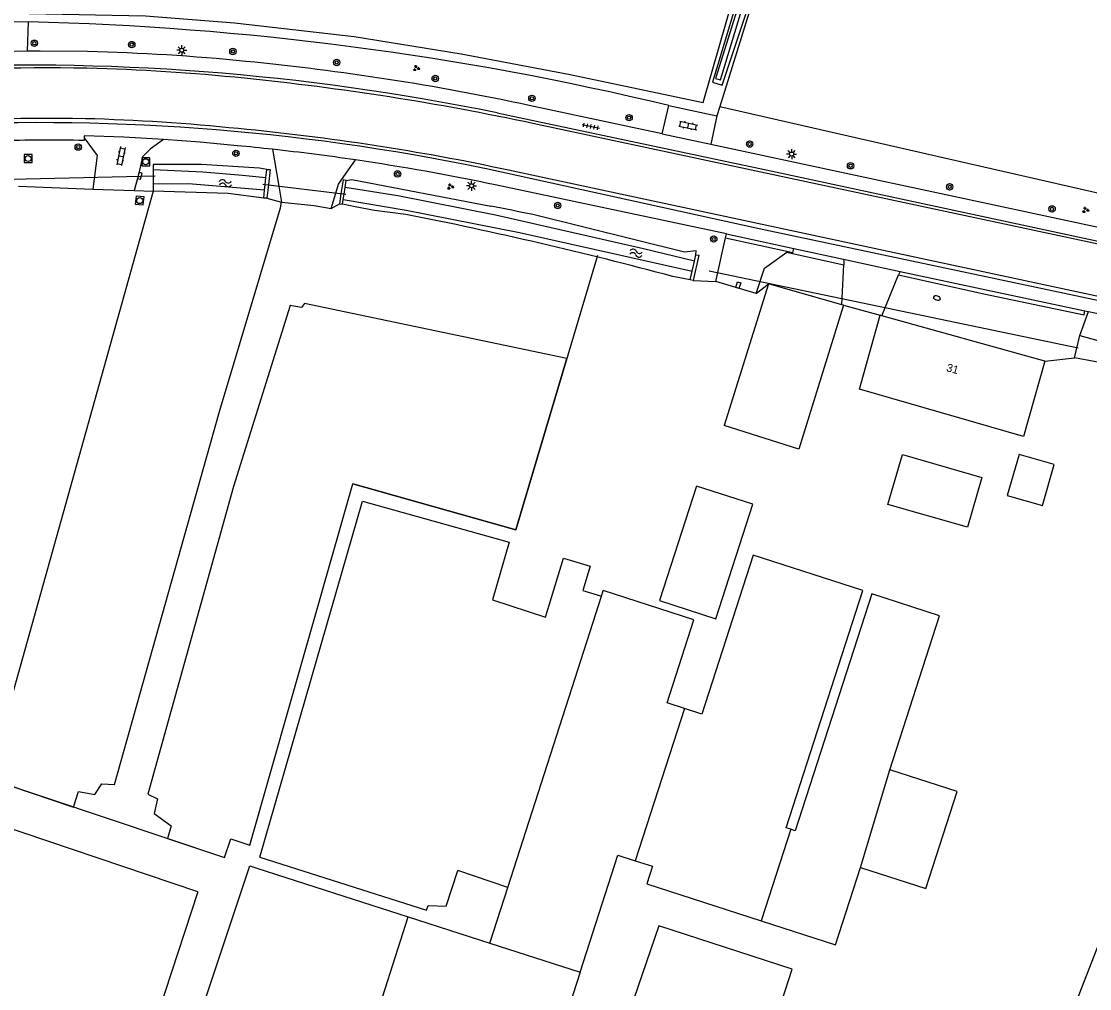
# Model space of a CAD drawing. Extents: x 136000 to 141014, y 402000 to 403500.
# Drawn here: x 136659.8 to 136793.3, y 402085 to 402205.8 of the extents above; entities that cross this region are included whole.
import ezdxf

# ---------------------------------------------------------------- set-up
doc = ezdxf.new("R2010")
doc.units = 0
for name, color, linetype in [('gg-afsc-draadraster', 7, 'Continuous'), ('gg-afsc-erfafscheiding', 7, 'Continuous'), ('gg-afsc-lijn draadraster', 7, 'Continuous'), ('gg-anno-huisnummerreeks BGT', 7, 'Continuous'), ('gg-bbg-bijgebouw', 7, 'Continuous'), ('gg-bbg-gedigitaliseerde bebouwing', 7, 'Continuous'), ('gg-bbg-gedigitaliseerde bijgebouw', 7, 'Continuous'), ('gg-bbg-hoofdgebouw', 7, 'Continuous'), ('gg-bbg-open loods', 7, 'Continuous'), ('gg-bbg-tussenscheiding', 7, 'Continuous'), ('gg-knt-bronhoudergrens', 7, 'Continuous'), ('gg-knt-verharding', 7, 'Continuous'), ('gg-kntw-bovenkant insteek waterloop', 7, 'Continuous'), ('gg-kntw-waterlijn', 7, 'Continuous'), ('gg-kwrk-duiker nz buis', 7, 'Continuous'), ('gg-kwrk-keermuur', 7, 'Continuous'), ('gt-grn-groengrens', 7, 'Continuous'), ('gt-grn-vlakafsluiter', 7, 'Continuous'), ('gt-symb-boom', 7, 'Continuous'), ('gt-symb-brandkraan', 7, 'Continuous'), ('gt-symb-groenvak', 7, 'Continuous'), ('gt-symb-klinker verharding', 7, 'Continuous'), ('gt-symb-kolk', 7, 'Continuous'), ('gt-symb-kolk center center', 7, 'Continuous'), ('gt-symb-lichtmast', 7, 'Continuous'), ('gt-symb-rioolschacht', 7, 'Continuous'), ('gt-symb-tegel verharding', 7, 'Continuous'), ('gt-symb-watersymbool', 7, 'Continuous')]:
    doc.layers.add(name, color=color, linetype=linetype)

# ---------------------------------------------------------------- blocks, each defined once
blk = doc.blocks.new('gt0-BR')
at = {"layer": 'gt-symb-brandkraan'}
for centre, radius, start, end in [((-0.24, 0), 0.206, 107.5669, 252.4331), ((0.6, -2.66), 3, 106.892, 107.5669), ((0, -0.69), 0.938, 73.108, 106.892), ((-0.6, -2.66), 3, 72.4331, 73.108), ((0.24, 0), 0.206, 287.567, 72.4331), ((0.6, 2.66), 3, 252.4331, 253.108), ((0, 0.69), 0.938, 253.108, 286.8921), ((-0.6, 2.66), 3, 286.8921, 287.567)]:
    blk.add_arc(centre, radius, start, end, dxfattribs=at)
blk = doc.blocks.new('gt0-KOLKCC')
at = {"layer": 'gt-symb-kolk center center'}
blk.add_lwpolyline([(-0.37, 0.2), (0.38, 0.2), (0.38, -0.2), (-0.37, -0.2)], close=True, dxfattribs=at)
blk = doc.blocks.new('gt0-GRVAK')
at = {"layer": 'gt-symb-groenvak'}
for p, q in [((-0.11, 0.19), (-0.23, 0.24)), ((-0.18, 0.15), (0.09, 0.15)), ((-0.09, 0.21), (-0.16, 0.32)), ((-0.05, 0.21), (-0.05, 0.39)), ((0, 0.21), (0.06, 0.32)), ((0.02, 0.19), (0.13, 0.24)), ((0.26, -0.05), (0.2, 0.06)), ((0.31, -0.05), (0.31, 0.13)), ((0.35, -0.05), (0.41, 0.06)), ((-0.24, -0.23), (-0.36, -0.18)), ((-0.32, -0.26), (-0.05, -0.26)), ((-0.23, -0.21), (-0.29, -0.1)), ((-0.18, -0.2), (-0.18, -0.02)), ((-0.14, -0.21), (-0.07, -0.1)), ((-0.12, -0.23), (0, -0.18)), ((0.24, -0.07), (0.12, -0.02)), ((0.17, -0.11), (0.44, -0.11)), ((0.37, -0.07), (0.49, -0.02))]:
    blk.add_line(p, q, dxfattribs=at)
blk = doc.blocks.new('gt0-BOOM')
at = {"layer": 'gt-symb-boom'}
for radius in [0.4, 0.2]:
    blk.add_circle((0, 0), radius, dxfattribs=at)
blk = doc.blocks.new('gt0-WA')
at = {"layer": 'gt-symb-watersymbool'}
for centre, start, end in [((-0.32, 0.02), 28.0725, 151.9275), ((0.43, 0.42), 208.0725, 331.9275), ((-0.32, -0.43), 28.0725, 151.9275), ((0.43, -0.03), 208.0725, 331.9275)]:
    blk.add_arc(centre, 0.425, start, end, dxfattribs=at)
blk = doc.blocks.new('gt0-LMAST')
at = {"layer": 'gt-symb-lichtmast'}
for p, q in [((-0.18, 0.17), (-0.45, 0.44)), ((0, 0.25), (0, 0.62)), ((0.17, 0.17), (0.44, 0.44)), ((-0.25, 0), (-0.63, 0)), ((-0.18, -0.18), (-0.45, -0.45)), ((0, -0.25), (0, -0.63)), ((0.44, -0.45), (0.17, -0.18)), ((0.25, 0), (0.62, 0))]:
    blk.add_line(p, q, dxfattribs=at)
blk.add_circle((0, 0), 0.25, dxfattribs=at)
blk = doc.blocks.new('gt0-TEG1')
at = {"layer": 'gt-symb-tegel verharding'}
for p, q in [((-1.12, 0), (1.12, 0)), ((-0.9, -0.25), (-0.9, 0.25)), ((-0.45, -0.25), (-0.45, 0.25)), ((0, -0.25), (0, 0.25)), ((0.45, -0.25), (0.45, 0.25)), ((0.9, -0.25), (0.9, 0.25))]:
    blk.add_line(p, q, dxfattribs=at)
blk = doc.blocks.new('gt0-KL1')
at = {"layer": 'gt-symb-klinker verharding'}
for p, q in [((-1.15, 0.3), (1.15, 0.3)), ((-1, -0.3), (-1, 0.3)), ((-0.5, 0.3), (-0.5, 0.45)), ((0, -0.3), (0, 0.3)), ((0.5, 0.3), (0.5, 0.45)), ((1, -0.3), (1, 0.3)), ((-1.15, -0.3), (1.15, -0.3)), ((-0.5, -0.45), (-0.5, -0.3)), ((0.5, -0.45), (0.5, -0.3))]:
    blk.add_line(p, q, dxfattribs=at)
blk = doc.blocks.new('gt0-RS')
at = {"layer": 'gt-symb-rioolschacht'}
blk.add_lwpolyline([(-0.5, -0.5), (0.5, -0.5), (0.5, 0.5), (-0.5, 0.5)], close=True, dxfattribs=at)
blk.add_circle((0, 0), 0.375, dxfattribs=at)
blk = doc.blocks.new('gt0-KOLK')
at = {"layer": 'gt-symb-kolk'}
blk.add_lwpolyline([(0, 0), (0.38, 0), (0.38, 0.4), (-0.37, 0.4), (-0.37, 0), (0, 0)], dxfattribs=at)

msp = doc.modelspace()

# ---------------------------------------------------------------- linework, layer by layer
at = {"layer": 'gg-afsc-draadraster'}
for p, q in [((136689.6, 402101.38), (136702.42, 402145.89)), ((136702.42, 402145.89), (136720.76, 402140.75))]:
    msp.add_line(p, q, dxfattribs=at)
at = {"layer": 'gg-afsc-erfafscheiding'}
for p, q in [((136659.43, 402185.22), (136668.71, 402184.88)), ((136668.71, 402184.88), (136673.89, 402184.69)), ((136673.89, 402184.69), (136676.28, 402184.61)), ((136792.06, 402166.6), (136793.15, 402169.58))]:
    msp.add_line(p, q, dxfattribs=at)
msp.add_arc((136651.79, 401826.29), 379.58, 76.4502, 88.6591, dxfattribs=at)
at = {"layer": 'gg-afsc-lijn draadraster'}
for p, q in [((136689.6, 402101.38), (136702.42, 402145.89)), ((136702.42, 402145.89), (136720.76, 402140.75))]:
    msp.add_line(p, q, dxfattribs=at)
for points in [[(136676.28, 402184.61), (136655.68, 402111.23), (136685.18, 402101.34), (136685.97, 402103.7), (136688.33, 402102.91), (136701.2, 402148.06)], [(136731.81, 402176.59), (136721.6, 402142.3), (136701.2, 402148.06)]]:
    msp.add_lwpolyline(points, dxfattribs=at)
at = {"layer": 'gg-bbg-bijgebouw'}
for p, q in [((136762.33, 402170.41), (136753.18, 402173.02)), ((136762.53, 402170.35), (136762.33, 402170.41)), ((136730.86, 402129.6), (136732.28, 402134.02)), ((136732.28, 402134.02), (136732.5, 402134.71)), ((136720.57, 402097.62), (136730.86, 402129.6)), ((136673.5, 402055.65), (136688.33, 402100.31)), ((136688.33, 402100.31), (136689.21, 402100.03)), ((136689.21, 402100.03), (136701.25, 402096.15)), ((136718.33, 402090.66), (136720.57, 402097.62)), ((136701.25, 402096.15), (136708.15, 402093.93)), ((136708.15, 402093.93), (136718.33, 402090.66))]:
    msp.add_line(p, q, dxfattribs=at)
msp.add_lwpolyline([(136784.93, 402066.17), (136803.05, 402112.68), (136826.4, 402103.59), (136808.29, 402057.08), (136784.93, 402066.17)], dxfattribs=at)
at = {"layer": 'gg-bbg-gedigitaliseerde bebouwing'}
msp.add_lwpolyline([(136787.69, 402163.36), (136785.02, 402153.97), (136764.52, 402159.86), (136767.13, 402169.1)], dxfattribs=at)
at = {"layer": 'gg-bbg-gedigitaliseerde bijgebouw'}
msp.add_line((136753.18, 402173.02), (136747.64, 402155.33), dxfattribs=at)
for points in [[(136762.53, 402170.35), (136756.95, 402152.38), (136747.64, 402155.33)], [(136768.09, 402145.48), (136769.89, 402151.71), (136779.84, 402148.85), (136778.05, 402142.62), (136768.09, 402145.48)], [(136783, 402146.6), (136787.41, 402145.34), (136788.88, 402150.45), (136784.47, 402151.72), (136783, 402146.6)], [(136739.55, 402133.45), (136746.6, 402131.18), (136751.22, 402145.49), (136744.17, 402147.77), (136739.55, 402133.45)], [(136755.94, 402104.88), (136755.38, 402105.06), (136764.95, 402134.72), (136751.24, 402139.15), (136744.82, 402119.27), (136742.65, 402119.97)], [(136742.65, 402119.97), (136740.49, 402120.66), (136743.84, 402131.05), (136732.5, 402134.71)], [(136768.33, 402112.32), (136774.53, 402131.54), (136766.06, 402134.28), (136756.51, 402104.7), (136755.94, 402104.88)], [(136764.65, 402100.1), (136772.81, 402097.46), (136776.74, 402109.61), (136768.33, 402112.32)], [(136729.62, 402087.02), (136734.35, 402101.65), (136736.51, 402100.95)], [(136736.51, 402100.95), (136738.68, 402100.25), (136737.96, 402098.04), (136752.24, 402093.42)], [(136752.24, 402093.42), (136761.52, 402090.43), (136764.65, 402100.1)], [(136729.62, 402087.02), (136715.15, 402042.2), (136693.68, 402049.13)]]:
    msp.add_lwpolyline(points, dxfattribs=at)
at = {"layer": 'gg-bbg-hoofdgebouw'}
for p, q in [((136767.32, 402169.05), (136767.13, 402169.1)), ((136787.69, 402163.36), (136767.32, 402169.05))]:
    msp.add_line(p, q, dxfattribs=at)
at = {"layer": 'gg-bbg-open loods'}
msp.add_lwpolyline([(136721.26, 402039.66), (136738.77, 402033.66), (136756.12, 402087.41), (136739.46, 402092.8), (136721.26, 402039.66)], dxfattribs=at)
at = {"layer": 'gg-bbg-tussenscheiding'}
for p, q in [((136742.65, 402119.97), (136736.51, 402100.95)), ((136764.65, 402100.1), (136768.33, 402112.32)), ((136755.94, 402104.88), (136752.24, 402093.42)), ((136693.68, 402049.13), (136708.15, 402093.93)), ((136718.33, 402090.66), (136729.62, 402087.02))]:
    msp.add_line(p, q, dxfattribs=at)
at = {"layer": 'gg-knt-bronhoudergrens'}
for p, q in [((136681.83, 402097.05), (136649.8, 402107.86)), ((136720.57, 402097.62), (136714.36, 402099.74)), ((136681.83, 402097.05), (136666.21, 402049.47))]:
    msp.add_line(p, q, dxfattribs=at)
for points in [[(136661.85, 402231.94), (136660.78, 402206.82), (136675.31, 402206.52), (136686.43, 402205.67), (136701.38, 402203.96), (136714.77, 402201.79), (136728.16, 402199.23), (136744.98, 402195.68), (136757.7, 402239.91), (136769.24, 402284.01), (136770.05, 402285.62), (136771.29, 402286.61), (136773.66, 402286.71)], [(136774, 402283.96), (136772.76, 402281.1), (136766.94, 402259.93), (136753.44, 402215.75), (136747.08, 402195.2)], [(136747.08, 402195.2), (136800.88, 402182.92), (136824.43, 402178.13), (136833.14, 402176.56), (136842.98, 402175.73)], [(136676.28, 402184.61), (136655.68, 402111.23), (136666.32, 402107.66), (136666.94, 402109.6), (136668.99, 402109.21), (136669.86, 402110.56), (136671.45, 402110.48), (136684.55, 402157.07), (136692.17, 402182.55), (136692.3, 402183.24)], [(136694.79, 402170.06), (136693.4, 402170.33), (136686.32, 402147.7), (136675.6, 402109.27), (136676.79, 402108.68), (136676.4, 402106.83), (136678.51, 402105.3), (136678.06, 402103.73), (136685.18, 402101.34), (136685.97, 402103.7), (136688.33, 402102.91), (136701.2, 402148.06), (136721.6, 402142.3), (136727.97, 402163.7), (136695.18, 402170.59), (136694.79, 402170.06)], [(136720.76, 402140.75), (136718.69, 402133.56), (136725.31, 402131.4)], [(136725.31, 402131.4), (136727.53, 402138.75), (136730.89, 402137.74), (136729.97, 402134.72), (136732.28, 402134.02)], [(136689.6, 402101.38), (136710.43, 402094.75), (136710.65, 402095.36), (136712.87, 402095.28), (136714.36, 402099.74)]]:
    msp.add_lwpolyline(points, dxfattribs=at)
at = {"layer": 'gg-knt-verharding'}
for p, q in [((136660.58, 402202.1), (136660.68, 402205.76)), ((136660.58, 402202.1), (136656.96, 402202.06)), ((136739.89, 402191.78), (136723.25, 402195.33)), ((136739.89, 402191.78), (136740.72, 402195.3)), ((136740.72, 402195.3), (136746.72, 402194.03)), ((136746.72, 402194.03), (136745.95, 402190.48)), ((136823.07, 402171.84), (136723.73, 402193.07)), ((136667.66, 402191.29), (136667.65, 402190.95)), ((136739.89, 402191.78), (136745.95, 402190.48)), ((136691.19, 402189.85), (136691.96, 402185.25)), ((136745.95, 402190.48), (136823.49, 402173.91)), ((136822.1, 402165.51), (136720.68, 402187.23)), ((136691.96, 402185.25), (136692.3, 402183.24)), ((136698.53, 402182.46), (136699.1, 402184.37)), ((136747.9, 402179.28), (136718.99, 402185.4)), ((136701.51, 402182.64), (136699.93, 402182.98)), ((136747.8, 402178.8), (136747.9, 402179.28)), ((136747.9, 402179.28), (136756.31, 402177.46)), ((136746.57, 402173.33), (136747.8, 402178.8)), ((136747.8, 402178.8), (136756.2, 402176.96)), ((136756.17, 402176.82), (136756.2, 402176.96)), ((136756.17, 402176.82), (136762.57, 402175.42)), ((136756.2, 402176.96), (136756.31, 402177.46)), ((136756.31, 402177.46), (136762.55, 402176.13)), ((136762.33, 402170.41), (136762.57, 402175.42)), ((136762.55, 402176.13), (136769.62, 402174.59)), ((136767.32, 402169.05), (136769.42, 402174.14)), ((136769.62, 402174.59), (136769.42, 402174.14)), ((136769.62, 402174.59), (136792.71, 402169.67)), ((136792.71, 402169.67), (136793.15, 402169.58)), ((136793.15, 402169.58), (136800.63, 402167.99))]:
    msp.add_line(p, q, dxfattribs=at)
for points in [[(136668.06, 402202.06), (136662.13, 402202.12), (136660.58, 402202.1)], [(136823.15, 402172.22), (136813.37, 402174.26), (136753.45, 402187.12), (136719.26, 402194.38)], [(136677.56, 402191.07), (136672.61, 402191.36), (136667.66, 402191.55), (136667.66, 402191.29)], [(136667.66, 402191.29), (136669.28, 402189.06), (136668.71, 402184.88)], [(136677.56, 402191.07), (136675.91, 402189.86), (136674.94, 402188.89), (136674.38, 402186.5), (136673.89, 402184.69)], [(136686.77, 402190.3), (136682.16, 402190.72), (136677.56, 402191.07)], [(136699.1, 402184.37), (136699.44, 402185.49), (136701.54, 402188.52)], [(136822.02, 402165.08), (136752.01, 402179.9), (136717.7, 402187.45)], [(136751.62, 402171.83), (136752.66, 402175.01), (136755.45, 402177.01), (136756.17, 402176.82)], [(136762.55, 402176.13), (136762.59, 402175.79), (136762.57, 402175.42)], [(136769.42, 402174.14), (136780.09, 402171.8), (136792.6, 402169.16), (136792.71, 402169.67)]]:
    msp.add_lwpolyline(points, dxfattribs=at)
for centre, radius, start, end in [((136662.16, 401945.6), 256.52, 84.2496, 88.682), ((136660.62, 401909.46), 290.9, 78.3707, 92.9687), ((136656.76, 401884.22), 318.14, 77.9351, 84.3894), ((136662.63, 401941.68), 258.34, 88.8109, 94.6618), ((136661.53, 401942.14), 257.91, 84.1789, 88.5648), ((136654.65, 401869.8), 330.57, 77.9381, 84.2641), ((136663.13, 401931.89), 261.82, 88.9796, 94.6249), ((136660.65, 401936.02), 257.75, 84.1486, 88.4124), ((136661.99, 401919.62), 273.56, 78.2514, 93.3983), ((136659.25, 401900.35), 293.39, 77.9138, 84.587), ((136662.95, 401939.1), 251.89, 88.9295, 91.3886), ((136660.3, 401907.33), 284.2, 83.7601, 84.6572), ((136660.45, 401908.43), 283.09, 81.6549, 83.7652), ((136660.48, 401908.97), 282.55, 78.0475, 81.645)]:
    msp.add_arc(centre, radius, start, end, dxfattribs=at)
at = {"layer": 'gg-kntw-bovenkant insteek waterloop'}
for p, q in [((136676.26, 402187.34), (136676.27, 402185.51)), ((136676.27, 402185.51), (136676.28, 402184.61)), ((136685.65, 402184.33), (136676.28, 402184.61)), ((136690.09, 402183.76), (136685.65, 402184.33)), ((136742.68, 402176.99), (136723.7, 402181.69)), ((136743.38, 402173.53), (136741.2, 402173.95)), ((136791.41, 402163.79), (136792.06, 402166.6)), ((136800.88, 402161.99), (136791.41, 402163.79))]:
    msp.add_line(p, q, dxfattribs=at)
for points in [[(136773.66, 402286.71), (136771.24, 402284.68), (136769.94, 402281.24), (136768.28, 402276.22), (136763.61, 402258.72), (136757.85, 402236.95), (136746.15, 402198.23), (136747.38, 402197.86), (136750.27, 402206.61), (136757.91, 402231.74), (136772.68, 402282.01), (136773.73, 402283.91), (136774, 402283.96)], [(136690.47, 402187.34), (136689.56, 402187.48), (136682.26, 402187.95), (136676.26, 402187.93), (136676.26, 402187.34)], [(136700.4, 402185.93), (136701.08, 402186.07), (136718.48, 402182.75)], [(136707.83, 402181.72), (136703.92, 402182.21), (136701.51, 402182.64)], [(136744.09, 402176.66), (136744.12, 402177.17), (136742.68, 402176.99)], [(136792.06, 402166.6), (136801.05, 402164.07), (136800.88, 402161.99)]]:
    msp.add_lwpolyline(points, dxfattribs=at)
for centre, radius, start, end in [((136608.35, 401678.26), 513.19, 74.9966, 78.8232), ((136657.81, 401870.72), 317.87, 78.0369, 78.9975)]:
    msp.add_arc(centre, radius, start, end, dxfattribs=at)
at = {"layer": 'gg-kntw-waterlijn'}
for points in [[(136857.3, 402299.04), (136856.79, 402298.9), (136829.4, 402293.82), (136807.27, 402289.42), (136789.24, 402286.16), (136775.48, 402285.99), (136773.98, 402285.8), (136773.31, 402285.6), (136772.05, 402284.35), (136770.94, 402282.37), (136767.06, 402268.6), (136762.31, 402251.22), (136755.72, 402228.7), (136751.24, 402213.71), (136746.56, 402198.71), (136747.18, 402198.53)], [(136747.18, 402198.53), (136758.71, 402236.69), (136765.53, 402258.48), (136770.25, 402276.77), (136771.47, 402281.15), (136772.65, 402283.98), (136773.76, 402284.98), (136775.86, 402285.27), (136789.12, 402285.39), (136798.74, 402287.12), (136840.34, 402295.34), (136849.65, 402297.05), (136856.83, 402298.17)], [(136676.26, 402187.34), (136682.46, 402187.05), (136687.42, 402186.62), (136690.36, 402186.31)], [(136690.2, 402184.74), (136680.68, 402185.53), (136676.27, 402185.51)], [(136743.9, 402175.85), (136737.54, 402177.41), (136719.05, 402181.62), (136706.83, 402184.04), (136700.27, 402185.09)], [(136700.02, 402183.57), (136707.9, 402182.23), (136722.05, 402179.44), (136737.87, 402175.93), (136743.63, 402174.63)]]:
    msp.add_lwpolyline(points, dxfattribs=at)
at = {"layer": 'gg-kwrk-duiker nz buis'}
for p, q in [((136631.16, 402185.45), (136676.51, 402186.55)), ((136689.99, 402185.49), (136700.33, 402184.22)), ((136745.73, 402174.65), (136791.86, 402165.04))]:
    msp.add_line(p, q, dxfattribs=at)
at = {"layer": 'gg-kwrk-keermuur'}
for p, q in [((136690.36, 402186.31), (136690.47, 402187.34)), ((136690.27, 402185.46), (136690.36, 402186.31)), ((136700.27, 402185.09), (136700.4, 402185.93)), ((136690.09, 402183.76), (136690.2, 402184.74)), ((136690.2, 402184.74), (136690.27, 402185.46)), ((136690.66, 402185.41), (136690.47, 402183.74)), ((136699.73, 402184.3), (136699.54, 402183.05)), ((136700.02, 402183.57), (136700.13, 402184.25)), ((136700.13, 402184.25), (136700.27, 402185.09)), ((136690.47, 402183.74), (136690.09, 402183.76)), ((136699.54, 402183.05), (136699.93, 402182.98)), ((136699.93, 402182.98), (136700.02, 402183.57)), ((136743.9, 402175.85), (136744.09, 402176.66)), ((136743.63, 402174.63), (136743.9, 402175.85)), ((136743.38, 402173.53), (136743.63, 402174.63)), ((136743.73, 402173.47), (136743.38, 402173.53))]:
    msp.add_line(p, q, dxfattribs=at)
for points in [[(136690.47, 402187.34), (136690.88, 402187.32), (136690.66, 402185.41)], [(136700.4, 402185.93), (136699.99, 402186.02), (136699.73, 402184.3)], [(136744.09, 402176.66), (136744.46, 402176.6), (136743.73, 402173.47)]]:
    msp.add_lwpolyline(points, dxfattribs=at)
at = {"layer": 'gt-grn-groengrens'}
for p, q in [((136747.08, 402195.2), (136746.72, 402194.03)), ((136787.69, 402163.36), (136791.41, 402163.79))]:
    msp.add_line(p, q, dxfattribs=at)
at = {"layer": 'gt-grn-vlakafsluiter'}
for p, q in [((136657.06, 402205.83), (136660.68, 402205.76)), ((136690.47, 402183.74), (136692.3, 402183.24)), ((136698.53, 402182.46), (136699.54, 402183.05)), ((136743.73, 402173.47), (136746.57, 402173.33)), ((136751.62, 402171.83), (136746.57, 402173.33)), ((136751.62, 402171.83), (136753.18, 402173.02)), ((136762.53, 402170.35), (136767.13, 402169.1))]:
    msp.add_line(p, q, dxfattribs=at)
msp.add_lwpolyline([(136692.3, 402183.24), (136696.38, 402182.83), (136698.53, 402182.46)], dxfattribs=at)

# ---------------------------------------------------------------- block references
at = {"layer": 'gt-symb-boom'}
for p in [(136661.42, 402203.1), (136673.59, 402202.93), (136686.23, 402202.07), (136699.2, 402200.69), (136711.52, 402198.69), (136723.6, 402196.21), (136735.74, 402193.8), (136750.81, 402190.5), (136666.9, 402190.12), (136686.61, 402189.34), (136763.42, 402187.79), (136706.81, 402186.77), (136775.8, 402185.16), (136726.82, 402182.82), (136788.6, 402182.4), (136746.32, 402178.64)]:
    msp.add_blockref('gt0-BOOM', p, dxfattribs=at)
at = {"layer": 'gt-symb-brandkraan', "rotation": -15.606930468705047}
msp.add_blockref('gt0-BR', (136774.21, 402171.27), dxfattribs=at)
at = {"layer": 'gt-symb-groenvak'}
for p in [(136709.14, 402199.98), (136713.41, 402185.18), (136792.78, 402182.26)]:
    msp.add_blockref('gt0-GRVAK', p, dxfattribs=at)
at = {"layer": 'gt-symb-klinker verharding'}
for p, rotation in [((136743.14, 402192.81), -12.006708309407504), ((136672.23, 402188.99), -101.53462065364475)]:
    msp.add_blockref('gt0-KL1', p, dxfattribs=dict(at, rotation=rotation))
at = {"layer": 'gt-symb-kolk', "rotation": -103.2438020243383}
msp.add_blockref('gt0-KOLK', (136674.4, 402186.58), dxfattribs=at)
at = {"layer": 'gt-symb-kolk center center', "rotation": 73.47156825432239}
msp.add_blockref('gt0-KOLKCC', (136749.39, 402172.86), dxfattribs=at)
at = {"layer": 'gt-symb-lichtmast'}
for p in [(136679.84, 402202.23), (136756.06, 402189.25), (136716.05, 402185.29)]:
    msp.add_blockref('gt0-LMAST', p, dxfattribs=at)
at = {"layer": 'gt-symb-rioolschacht'}
for p in [(136660.64, 402188.69), (136675.34, 402188.3)]:
    msp.add_blockref('gt0-RS', p, dxfattribs=at)
at = {"layer": 'gt-symb-rioolschacht', "rotation": -5.453918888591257}
msp.add_blockref('gt0-RS', (136674.58, 402183.44), dxfattribs=at)
at = {"layer": 'gt-symb-tegel verharding', "rotation": -11.770626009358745}
msp.add_blockref('gt0-TEG1', (136730.96, 402192.7), dxfattribs=at)
at = {"layer": 'gt-symb-watersymbool'}
for p, rotation in [((136685.23, 402185.62), 0.973934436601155), ((136736.56, 402176.89), -7.004259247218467)]:
    msp.add_blockref('gt0-WA', p, dxfattribs=dict(at, rotation=rotation))

# ---------------------------------------------------------------- texts
at = {"layer": 'gg-anno-huisnummerreeks BGT'}
msp.add_text('31', height=1, rotation=344.4, dxfattribs=at).set_placement((136775.33, 402162.14))

doc.saveas('drawing.dxf')
